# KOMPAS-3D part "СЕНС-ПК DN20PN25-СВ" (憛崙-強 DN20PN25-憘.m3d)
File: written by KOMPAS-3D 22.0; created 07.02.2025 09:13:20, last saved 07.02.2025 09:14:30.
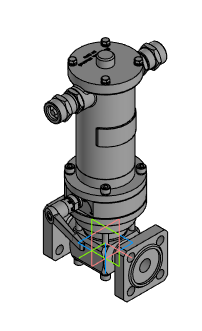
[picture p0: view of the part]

Document properties: Автор: setup; Полное имя файла: \\10.10.77.77\!! users\Савин А.Г\!Клапаны 3D для заказчика\СЕНС-ПК\1. СЕНС-ПК\СЕНС-ПК DN20PN25-СВ.m3d

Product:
- Body: Тело 3
    Масса: 9.898204
- Part/product: СЕНС-ПК DN20PN25-СВ
    Масса: 9.704967

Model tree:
1. Операция без истории:1
2. Эскиз:1  (with: Операция без истории:1)
3. Элемент выдавливания:1
     Расстояние 1 = 14
4. Фаска:1  (with: Элемент выдавливания:1)
     Угол = 45; Длина 1 = 2; Длина 2 = 2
